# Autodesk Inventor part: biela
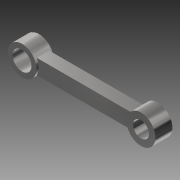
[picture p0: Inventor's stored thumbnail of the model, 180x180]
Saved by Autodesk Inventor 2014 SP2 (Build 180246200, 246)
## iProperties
Created: 2016-04
Part Number: biela
Material: Genérico
Document SubType Name: Modeling
Designer: Celiberto
Density: 1 g/cm^3
Appearance: Aço - Polido
Mass: 0.250783 g
Surface Area: 4.53627 cm^2
Volume: 0.250783 cm^3
Author: Celiberto
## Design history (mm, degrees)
sketch "Esboço1"
  geometry: L1 (-11.9, 1.5)-(11.9, 1.5); L2 (11.9, 1.5)-(11.9, -1.5); L3 (11.9, -1.5)-(-11.9, -1.5); L4 (-11.9, -1.5)-(-11.9, 1.5); L5 (-11.9, 1.5)-(11.9, -1.5); L6 (11.9, 1.5)-(-11.9, -1.5); 1 further point
  constraints: 12 end point, 2 midpoint, 2 parallel, 1 horizontal, 1 perpendicular
  dimensions: "d0" = 23.8 distance between parallel lines of L2 L4; "d1" = 3 distance between parallel lines of L3 L1
extrude "Extrusão1" new body sketch "Esboço1" stored distance "d2" = 2.5; taper "d3" = 0 deg
sketch "Esboço2"
  geometry: L1 (-11.9, -1.5)-(11.9, -1.5) reference; L2 (11.9, -1.5)-(11.9, 1.5) reference; L3 (11.9, 1.5)-(-11.9, 1.5) reference; L4 (-11.9, 1.5)-(-11.9, -1.5) reference; L5 (-11.9, -1.5)-(-11.9, 1.5) reference; L6 (11.9, 1.5)-(11.9, -1.5) reference; 1 further point
sketch "Esboço3"
  geometry: L1 (-11.9, 1.5)-(-11.9, -1.5) reference; L2 (11.9, -1.5)-(11.9, 1.5) reference; C1 r 2.9 at (-11.9, 0); C2 r 2.9 at (11.9, 0); 1 further point
  constraints: 2 centre point, 2 midpoint
  dimensions: "d4" = 5.8 diameter of C1; "d5" = 5.8 diameter of C2
extrude "Extrusão2" join sketch "Esboço3" stored distance "d6" = 3.4; taper "d7" = 0 deg
sketch "Esboço4"
  geometry: C1 r 2.9 at (0, 0) reference; 2 further points
  constraints: 1 coincident
hole "Furo1" sketch "Esboço4" at (0, 0) diameter "d8" = 3.2; stored, may be unused: countersink angle "d12" = 90 deg, drill point angle "d14" = 118 deg; dims "d9" = 6, "d10" = 4, "d11" = 2, "d13" = 8
sketch "Esboço5"
  geometry: C1 r 2.9 at (0, 0) reference; 2 further points
  constraints: 1 coincident
hole "Furo2" sketch "Esboço5" at (0, 0) diameter "d15" = 3.8; stored, may be unused: countersink angle "d19" = 90 deg, drill point angle "d21" = 118 deg; dims "d16" = 6, "d17" = 4, "d18" = 2, "d20" = 8
node "Sólido1"
